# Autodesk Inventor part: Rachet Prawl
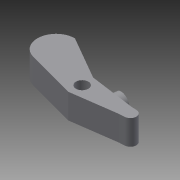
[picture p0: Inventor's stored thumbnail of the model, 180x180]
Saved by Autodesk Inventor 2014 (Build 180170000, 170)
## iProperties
Created: 2013-11
Part Number: Rachet Prawl
Material: Generic
Document SubType Name: Modeling
Designer: 603839
Density: 1 g/cm^3
Appearance: Default
Mass: 7.3567 g
Surface Area: 30.8961 cm^2
Volume: 7.3567 cm^3
Author: 603839
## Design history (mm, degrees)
sketch "Sketch7"
  geometry: L1 (25.4, -6.35)-(0.002, -3.175); L2 (25.4, 6.35)-(0, 3.175); L3 (25.4, -6.35)-(49.935, -12.924); L4 (25.4, 6.35)-(49.935, -0.224); L5 (25.4, 6.35)-(50.8, 6.35); A1 r 3.175 centre (0, 0) between (0, 3.175) and (0.002, -3.175); A2 r 6.574 centre (48.233, -6.574) between (49.935, -12.924) and (49.935, -0.224); 1 further point
  constraints: 10 end point, 4 point on circle, 2 centre point, 1 coincident, 1 equal length, 1 horizontal, 1 parallel, 1 tangent
  dimensions: "d13" = 6.35 diameter of A1; "d25" = 25.4 distance of L1.start L3.end; "d27" = 25.4 distance of L2.start L4.end; "d28" = 15 deg angle of L4 L5 (derived)
extrude "Extrusion5" new body sketch "Sketch7" distance "d19" = 12.7; taper "d20" = 0 deg
hole "Hole1" diameter "d31" = 6.35; stored, may be unused: countersink angle "d35" = 82 deg, drill point angle "d37" = 118 deg; dims "d29" = 6.35, "d30" = 25.4, "d32" = 19.05, "d33" = 9.525, "d34" = 6.35, "d36" = 25.4
sketch "Sketch8"
  geometry: L1 (-0.002, 3.175)-(-25.4, 6.35) reference; L2 (-25.4, -6.35)-(0, -3.175) reference; L3 (-0.002, 3.175)-(-2.522, 3.49); L4 (-0.002, 3.175)-(-2.542, 3.175); L5 (0, -3.175)-(-2.54, -3.175); L6 (-2.54, -3.175)-(-25.4, -6.35); L7 (-2.542, 3.175)-(-25.4, 6.35); A1 r 3.175 centre (0, 0) between (0, -3.175) and (-0.002, 3.175) reference
  constraints: 10 end point, 1 horizontal, 1 parallel, 1 point on line, 1 tangent
  dimensions: "d39" = 2.54 distance of L1.start L4.end; "d40" = 2.54 distance of L2.end L5.end
extrude "Extrusion6" cut sketch "Sketch8" stored distance "d41" = 6.35; taper "d42" = 0 deg
sketch "Sketch10"
  geometry: L1 (0, 0)-(0, 12.7) reference; L2 (0, 6.35)-(6.35, 6.35); C1 r 5.715 at (6.35, 6.35); 1 further point
  constraints: 2 end point, 1 centre point, 1 coincident, 1 midpoint, 1 perpendicular
  dimensions: "d47" = 6.35 distance of L2.start L2.end; "d48" = 11.43 diameter of C1
extrude "Extrusion8" cut sketch "Sketch10" distance "d49" = 6.35; taper "d50" = 0 deg
sketch "Sketch11"
  geometry: L1 (-25.4, -6.35)-(-2.54, -3.175) reference; L2 (-2.54, -3.175)-(0, -3.175) reference; L3 (-0.002, 3.175)-(-2.542, 3.175) reference; L4 (-2.542, 3.175)-(-25.4, 6.35) reference; L5 (-25.4, 6.35)-(-49.935, 12.924) reference; L6 (-49.935, 0.224)-(-25.4, -6.35) reference; L7 (-25.4, 6.35)-(-47.397, 19.05); L8 (-25.4, 6.35)-(0, 6.35); A1 r 3.175 centre (0, 0) between (0, -3.175) and (-0.002, 3.175) reference; A2 r 6.574 centre (-48.233, 6.574) between (-49.935, 12.924) and (-49.935, 0.224) reference; A3 r 9.576 centre (-47.456, 9.474) between (-47.397, 19.05) and (-49.935, 0.224)
  constraints: 4 end point, 2 point on circle, 1 centre point, 1 equal length, 1 horizontal, 1 tangent
  dimensions: "d51" = 25.4 distance of L4.end L7.end; "d52" = 150 deg angle of L8 L7
extrude "Extrusion9" join sketch "Sketch11" stored distance "d53" = 25.4; taper "d54" = 0 deg
sketch "Sketch12"
  geometry: L1 (-2.54, -3.175)-(0, -3.175) reference; L2 (-0.002, 3.175)-(-2.542, 3.175) reference; L3 (-2.542, 3.175)-(0, 3.048); L4 (-2.54, -3.175)-(0, -3.048); A1 r 3.175 centre (0, 0) between (0, -3.175) and (-0.002, 3.175) reference; A2 r 3.048 centre (0, 0) between (0, -3.048) and (0, 3.048)
  constraints: 4 end point, 2 point on circle, 1 centre point, 1 coincident
  dimensions: "d55" = 6.096 diameter of A2
extrude "Extrusion10" cut sketch "Sketch12" distance "d56" = 25.4; taper "d57" = 0 deg
sketch "Sketch13"
  geometry: C1 r 5.715 at (0, 0) reference; 1 further point
extrude "Extrusion11" join sketch "Sketch13" stored distance "d58" = 25.4; taper "d59" = 0 deg
sketch "Sketch14"
  geometry: C1 r 4.445 at (-11.539, 6.35); 1 further point
  constraints: 1 centre point
  dimensions: "d60" = 8.89 diameter of C1
extrude "Extrusion12" join sketch "Sketch14" distance "d61" = 4.445; taper "d62" = 0 deg
body "Solid2"
